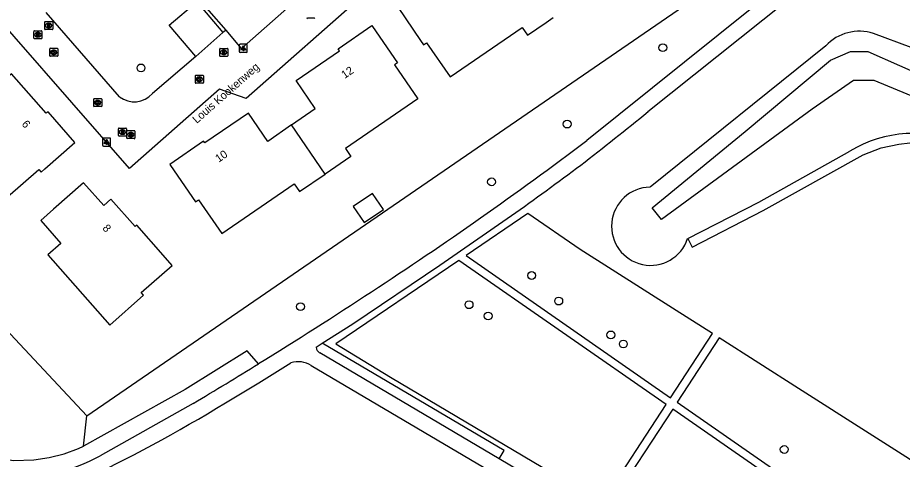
# Model space of a CAD drawing. Extents: x 159353 to 160616, y 385893 to 387321.
# Drawn here: x 160134.7 to 160245.3, y 386306.6 to 386361.8 of the extents above; entities that cross this region are included whole.
import ezdxf

# ---------------------------------------------------------------- set-up
doc = ezdxf.new("R2010")
doc.units = 0
for name, color, linetype in [('IMGEO_Boom', 7, 'Continuous'), ('IMGEO_Groenvoorziening', 7, 'Continuous'), ('IMGEO_Haag', 7, 'Continuous'), ('IMGEO_Kolk', 7, 'Continuous'), ('IMGEO_Lichtpunt', 7, 'Continuous'), ('IMGEO_Openbare_ruimte_label', 7, 'Continuous'), ('IMGEO_Pand', 7, 'Continuous'), ('IMGEO_Pand_nummerreeks', 7, 'Continuous'), ('IMGEO_Parkeervlak_open', 7, 'Continuous'), ('IMGEO_Rijbaan_lokaal_open', 7, 'Continuous'), ('IMGEO_Rioolput', 7, 'Continuous'), ('IMGEO_Voetpad_halfverhard', 7, 'Continuous'), ('IMGEO_Waterloop', 7, 'Continuous')]:
    doc.layers.add(name, color=color, linetype=linetype)

msp = doc.modelspace()

# ---------------------------------------------------------------- linework, layer by layer
at = {"layer": 'IMGEO_Boom'}
for centre in [(160215.37, 386358.02), (160150.15, 386355.49), (160203.41, 386348.48), (160193.96, 386341.26), (160198.98, 386329.57), (160202.36, 386326.38), (160170.08, 386325.68), (160191.15, 386325.92), (160193.53, 386324.52), (160208.87, 386322.15), (160210.44, 386321.02), (160230.54, 386307.85)]:
    msp.add_circle(centre, 0.489, dxfattribs=at)
at = {"layer": 'IMGEO_Groenvoorziening'}
for points in [[(160160.77, 386360.2), (160154.42, 386367.49)], [(160143.38, 386312.04), (160220.76, 386365.17)], [(160255.91, 386354.23), (160246.39, 386358.04), (160241.7, 386359.78)], [(160235.73, 386358.24), (160213.77, 386340.6)], [(160198.49, 386337.31), (160190.77, 386332.07), (160216.33, 386314.31), (160221.56, 386322.32), (160217.05, 386325.2), (160205.04, 386332.82), (160198.49, 386337.31)], [(160207.73, 386301.15), (160215.78, 386313.47), (160189.88, 386331.46), (160174.51, 386321.02), (160181.32, 386316.87), (160202.6, 386304.25), (160207.73, 386301.15)], [(160143.38, 386312.04), (160131.39, 386324.81)], [(160268.79, 386292.3), (160268.59, 386292.42), (160232.33, 386315.45), (160222.41, 386321.79), (160217.15, 386313.74), (160259.75, 386284.14), (160259.95, 386284.01), (160261.35, 386283.03)], [(160164.85, 386318.56), (160163.42, 386320.18), (160155.66, 386315.33), (160142.96, 386308.28)], [(160260.41, 386282.47), (160259.01, 386283.44), (160258.82, 386283.57), (160216.6, 386312.9), (160208.58, 386300.63), (160213.71, 386297.53), (160238.42, 386282.67), (160246.05, 386278.11)], [(160142.96, 386308.28), (160143.38, 386312.04)], [(160130.97, 386307), (160134.22, 386306.46), (160136.77, 386306.56), (160138.67, 386306.83), (160140.54, 386307.31), (160142.34, 386307.97), (160142.96, 386308.28)]]:
    msp.add_lwpolyline(points, dxfattribs=at)
for centre, radius, start, end in [((160239.91, 386354.4), 5.67, 71.5561, 137.4262), ((160213.84, 386335.72), 4.88, 90.9182, 341.6011)]:
    msp.add_arc(centre, radius, start, end, dxfattribs=at)
at = {"layer": 'IMGEO_Haag'}
for points in [[(160218.48, 386334.18), (160219.02, 386333.11), (160227.93, 386337.67), (160240.41, 386344.64), (160242.65, 386345.53), (160244.86, 386345.99), (160246.24, 386346.12)], [(160218.48, 386334.18), (160227.36, 386338.73), (160238.75, 386345.09)], [(160194.91, 386306.66), (160195.52, 386307.7), (160172.8, 386321.12)]]:
    msp.add_lwpolyline(points, dxfattribs=at)
msp.add_arc((160246.7, 386332.01), 15.31, 65.4867, 121.2918, dxfattribs=at)
at = {"layer": 'IMGEO_Kolk'}
for p, q in [((160171.79, 386361.69), (160170.94, 386361.69)), ((160138.74, 386357.02), (160138.74, 386357.87)), ((160138.81, 386357.94), (160139.67, 386357.94)), ((160139.74, 386357.87), (160139.74, 386357.02)), ((160139.67, 386356.94), (160138.81, 386356.94)), ((160139.23, 386357.72), (160139.25, 386357.72)), ((160139.25, 386357.16), (160139.23, 386357.16)), ((160156.94, 386353.66), (160156.94, 386354.51)), ((160157.01, 386354.59), (160157.86, 386354.59)), ((160157.94, 386354.51), (160157.94, 386353.66)), ((160157.86, 386353.58), (160157.01, 386353.58)), ((160157.42, 386354.36), (160157.45, 386354.36)), ((160157.45, 386353.81), (160157.42, 386353.81)), ((160144.24, 386350.73), (160144.24, 386351.58)), ((160144.31, 386351.66), (160145.16, 386351.66)), ((160144.72, 386351.44), (160144.75, 386351.44)), ((160145.24, 386351.58), (160145.24, 386350.73)), ((160145.16, 386350.66), (160144.31, 386350.66)), ((160144.75, 386350.88), (160144.72, 386350.88))]:
    msp.add_line(p, q, dxfattribs=at)
for points in [[(160171.79, 386361.69), (160170.94, 386361.69)], [(160138.74, 386357.02), (160138.74, 386357.87)], [(160138.81, 386357.94), (160139.67, 386357.94)], [(160139.74, 386357.87), (160139.74, 386357.02)], [(160139.67, 386356.94), (160138.81, 386356.94)], [(160139.06, 386357.64), (160139.18, 386357.64), (160139.18, 386357.49), (160139.31, 386357.64), (160139.48, 386357.64), (160139.33, 386357.49), (160139.48, 386357.24), (160139.33, 386357.24), (160139.25, 386357.41), (160139.18, 386357.34), (160139.18, 386357.24), (160139.06, 386357.24), (160139.06, 386357.64)], [(160156.94, 386353.66), (160156.94, 386354.51)], [(160157.01, 386354.59), (160157.86, 386354.59)], [(160157.94, 386354.51), (160157.94, 386353.66)], [(160157.86, 386353.58), (160157.01, 386353.58)], [(160157.26, 386354.28), (160157.38, 386354.28), (160157.38, 386354.13), (160157.51, 386354.28), (160157.67, 386354.28), (160157.53, 386354.13), (160157.68, 386353.88), (160157.53, 386353.88), (160157.44, 386354.05), (160157.38, 386353.98), (160157.38, 386353.88), (160157.26, 386353.88), (160157.26, 386354.28)], [(160144.24, 386350.73), (160144.24, 386351.58)], [(160144.31, 386351.66), (160145.16, 386351.66)], [(160144.56, 386351.36), (160144.68, 386351.36), (160144.68, 386351.21), (160144.81, 386351.36), (160144.97, 386351.36), (160144.83, 386351.21), (160144.98, 386350.96), (160144.83, 386350.96), (160144.74, 386351.12), (160144.68, 386351.06), (160144.68, 386350.96), (160144.56, 386350.96), (160144.56, 386351.36)], [(160145.24, 386351.58), (160145.24, 386350.73)], [(160145.16, 386350.66), (160144.31, 386350.66)]]:
    msp.add_lwpolyline(points, dxfattribs=at)
for centre, start, end in [((160170.94, 386361.76), 181.552, 268.448), ((160170.94, 386361.76), 181.552, 268.448), ((160171.79, 386361.76), 271.552, 358.448), ((160171.79, 386361.76), 271.552, 358.448), ((160138.82, 386357.87), 91.552, 178.448), ((160138.82, 386357.87), 91.552, 178.448), ((160139.66, 386357.87), 1.552, 88.448), ((160139.66, 386357.87), 1.552, 88.448), ((160138.82, 386357.02), 181.552, 268.448), ((160138.82, 386357.02), 181.552, 268.448), ((160139.66, 386357.02), 271.552, 358.448), ((160139.66, 386357.02), 271.552, 358.448), ((160157.01, 386354.51), 91.552, 178.448), ((160157.01, 386354.51), 91.552, 178.448), ((160157.86, 386354.51), 1.552, 88.448), ((160157.86, 386354.51), 1.552, 88.448), ((160157.01, 386353.66), 181.552, 268.448), ((160157.01, 386353.66), 181.552, 268.448), ((160157.86, 386353.66), 271.552, 358.448), ((160157.86, 386353.66), 271.552, 358.448), ((160144.31, 386351.58), 91.552, 178.448), ((160144.31, 386351.58), 91.552, 178.448), ((160145.16, 386351.58), 1.552, 88.448), ((160145.16, 386351.58), 1.552, 88.448), ((160144.31, 386350.73), 181.552, 268.448), ((160144.31, 386350.73), 181.552, 268.448), ((160145.16, 386350.73), 271.552, 358.448), ((160145.16, 386350.73), 271.552, 358.448)]:
    msp.add_arc(centre, 0.0765, start, end, dxfattribs=at)
for centre, major_axis, ratio, start_param, end_param in [((160139.23, 386357.44), (-0.387, 0.002), 0.722429, 4.712389, 7.853982), ((160139.25, 386357.44), (-0.39, 0.002), 0.717154, 1.570796, 4.712389), ((160157.42, 386354.08), (-0.387, 0.002), 0.722429, 4.712389, 7.853982), ((160157.45, 386354.08), (-0.39, 0.002), 0.717154, 1.570796, 4.712389), ((160144.72, 386351.16), (-0.387, 0.002), 0.722429, 4.712389, 7.853982), ((160144.75, 386351.16), (-0.39, 0.002), 0.717154, 1.570796, 4.712389)]:
    msp.add_ellipse(centre, major_axis=major_axis, ratio=ratio, start_param=start_param, end_param=end_param, dxfattribs=at)
at = {"layer": 'IMGEO_Lichtpunt'}
for p, q in [((160162.43, 386358.34), (160162.43, 386357.53)), ((160162.43, 386358.34), (160162.43, 386357.53)), ((160163.33, 386358.44), (160162.52, 386358.44)), ((160163.33, 386358.44), (160162.52, 386358.44)), ((160163.42, 386357.53), (160163.42, 386358.34)), ((160163.42, 386357.53), (160163.42, 386358.34)), ((160162.52, 386357.44), (160163.33, 386357.44)), ((160162.52, 386357.44), (160163.33, 386357.44)), ((160146.25, 386346.74), (160145.44, 386346.74)), ((160146.25, 386346.74), (160145.44, 386346.74)), ((160145.35, 386346.64), (160145.35, 386345.84)), ((160145.35, 386346.64), (160145.35, 386345.84)), ((160145.44, 386345.74), (160146.25, 386345.74)), ((160145.44, 386345.74), (160146.25, 386345.74)), ((160146.35, 386345.84), (160146.35, 386346.64)), ((160146.35, 386345.84), (160146.35, 386346.64))]:
    msp.add_line(p, q, dxfattribs=at)
for points in [[(160162.8, 386358), (160162.84, 386357.98), (160162.65, 386357.71), (160162.61, 386357.74), (160162.8, 386358)], [(160162.9, 386357.96), (160162.95, 386357.96), (160162.95, 386357.63), (160162.9, 386357.63), (160162.9, 386357.96)], [(160163.01, 386357.98), (160163.05, 386358), (160163.24, 386357.74), (160163.2, 386357.71), (160163.01, 386357.98)], [(160145.72, 386346.31), (160145.76, 386346.28), (160145.58, 386346.02), (160145.54, 386346.04), (160145.72, 386346.31)], [(160145.83, 386346.26), (160145.87, 386346.26), (160145.87, 386345.94), (160145.83, 386345.94), (160145.83, 386346.26)], [(160145.94, 386346.28), (160145.97, 386346.31), (160146.16, 386346.04), (160146.12, 386346.02), (160145.94, 386346.28)]]:
    msp.add_lwpolyline(points, dxfattribs=at)
for centre in [(160162.93, 386358.14), (160145.85, 386346.44)]:
    msp.add_circle(centre, 0.0994, dxfattribs=at)
for centre, start, end in [((160162.52, 386358.34), 90, 180), ((160162.52, 386358.34), 90, 180), ((160163.33, 386358.34), 0, 90), ((160163.33, 386358.34), 0, 90), ((160162.52, 386357.53), 180, 270), ((160162.52, 386357.53), 180, 270), ((160163.33, 386357.53), 270, 0), ((160163.33, 386357.53), 270, 360), ((160145.44, 386346.64), 90, 180), ((160145.44, 386346.64), 90, 180), ((160146.25, 386346.64), 0, 90), ((160146.25, 386346.64), 0, 90), ((160145.44, 386345.84), 180, 270), ((160145.44, 386345.84), 180, 270), ((160146.25, 386345.84), 270, 0), ((160146.25, 386345.84), 270, 360)]:
    msp.add_arc(centre, 0.0946, start, end, dxfattribs=at)
at = {"layer": 'IMGEO_Pand'}
for points in [[(160197.61, 386367.69), (160194.65, 386365.65), (160192.06, 386369.4), (160186.63, 386365.67), (160186.47, 386365.91), (160182.27, 386363.03), (160185.1, 386358.91), (160185.46, 386358.38), (160185.83, 386358.64), (160188.78, 386354.36), (160197.8, 386360.56), (160198.47, 386359.59), (160200.78, 386361.18), (160201.67, 386361.79)], [(160168.95, 386348.37), (160171.91, 386350.41), (160169.53, 386353.91), (160174.94, 386357.63), (160174.79, 386357.88), (160179.01, 386360.77), (160181.84, 386356.65), (160182.2, 386356.13), (160181.83, 386355.87), (160184.74, 386351.63), (160175.72, 386345.42), (160176.39, 386344.45), (160173.16, 386342.24)], [(160122.81, 386349.79), (160125.36, 386346.87), (160126.25, 386347.65), (160133.46, 386339.41), (160137.36, 386342.82), (160137.65, 386342.49), (160138.12, 386342.9), (160141.89, 386346.19), (160138.54, 386350.01), (160138.31, 386349.83), (160133.96, 386354.77), (160130.76, 386351.98), (160128.39, 386354.68)], [(160168.95, 386348.37), (160165.99, 386346.32), (160163.57, 386349.83), (160158.11, 386346.12), (160157.97, 386346.33), (160153.77, 386343.43), (160156.6, 386339.31), (160156.96, 386338.79), (160157.33, 386339.04), (160160.25, 386334.8), (160169.29, 386341.01), (160169.96, 386340.04), (160173.16, 386342.24)], [(160173.16, 386342.24), (160168.95, 386348.37)], [(160150.47, 386327.1), (160150.17, 386327.44), (160154.04, 386330.84), (160152.92, 386332.12), (160149.61, 386335.87), (160149.41, 386335.69), (160146.39, 386339.1), (160145.48, 386338.3), (160142.97, 386341.15), (160139.22, 386337.85), (160137.61, 386336.43), (160140.12, 386333.58), (160138.5, 386332.15), (160146.23, 386323.37), (160150.47, 386327.1)], [(160180.45, 386337.83), (160179.07, 386339.83), (160176.68, 386338.19), (160178.05, 386336.19), (160180.45, 386337.83)]]:
    msp.add_lwpolyline(points, dxfattribs=at)
at = {"layer": 'IMGEO_Parkeervlak_open'}
msp.add_lwpolyline([(160156.99, 386356.93), (160153.67, 386360.81), (160157.12, 386363.75), (160160.38, 386359.93)], dxfattribs=at)
at = {"layer": 'IMGEO_Rijbaan_lokaal_open'}
for points in [[(160199.4, 386380.85), (160179.64, 386363.49), (160178.33, 386364.97), (160163.29, 386351.69), (160159.97, 386352.84), (160148.7, 386342.92), (160127.04, 386367.69), (160141.86, 386380.85), (160145.8, 386393.31)], [(160197.43, 386383.17), (160193.87, 386380.06), (160192.54, 386381.54), (160183.44, 386373.54), (160182.14, 386375.08), (160162.71, 386357.93), (160160.77, 386360.2)], [(160147.47, 386351.9), (160138.29, 386362.43)], [(160160.77, 386360.2), (160160.38, 386359.93)], [(160160.38, 386359.93), (160156.99, 386356.93)], [(160156.99, 386356.93), (160151.57, 386352.3)]]:
    msp.add_lwpolyline(points, dxfattribs=at)
msp.add_arc((160149.31, 386354.22), 2.96, 231.5618, 319.6293, dxfattribs=at)
at = {"layer": 'IMGEO_Rioolput'}
for p, q in [((160138.11, 386360.35), (160138.11, 386361.21)), ((160138.18, 386361.28), (160139.03, 386361.28)), ((160139.11, 386361.21), (160139.11, 386360.35)), ((160136.76, 386359.21), (160136.76, 386360.06)), ((160136.84, 386360.13), (160137.69, 386360.13)), ((160137.76, 386360.06), (160137.76, 386359.21)), ((160139.03, 386360.28), (160138.18, 386360.28)), ((160138.62, 386360.5), (160138.59, 386360.5)), ((160138.6, 386361.06), (160138.62, 386361.06)), ((160137.69, 386359.13), (160136.84, 386359.13)), ((160137.25, 386359.91), (160137.27, 386359.91)), ((160137.27, 386359.35), (160137.25, 386359.35)), ((160159.98, 386357.01), (160159.98, 386357.86)), ((160160.06, 386357.93), (160160.91, 386357.93)), ((160160.98, 386357.86), (160160.98, 386357.01)), ((160160.91, 386356.93), (160160.06, 386356.93)), ((160160.47, 386357.71), (160160.49, 386357.71)), ((160160.49, 386357.15), (160160.47, 386357.15)), ((160147.32, 386347.05), (160147.32, 386347.9)), ((160147.39, 386347.98), (160148.25, 386347.98)), ((160148.32, 386347.9), (160148.32, 386347.05)), ((160148.25, 386346.98), (160147.39, 386346.98)), ((160147.83, 386347.2), (160147.8, 386347.2)), ((160147.81, 386347.76), (160147.83, 386347.76)), ((160148.38, 386346.73), (160148.38, 386347.58)), ((160148.45, 386347.66), (160149.31, 386347.66)), ((160148.89, 386346.88), (160148.86, 386346.88)), ((160148.87, 386347.44), (160148.89, 386347.44)), ((160149.38, 386347.58), (160149.38, 386346.73)), ((160149.31, 386346.66), (160148.45, 386346.66))]:
    msp.add_line(p, q, dxfattribs=at)
for points in [[(160138.11, 386360.35), (160138.11, 386361.21)], [(160138.18, 386361.28), (160139.03, 386361.28)], [(160139.11, 386361.21), (160139.11, 386360.35)], [(160136.76, 386359.21), (160136.76, 386360.06)], [(160136.84, 386360.13), (160137.69, 386360.13)], [(160137.76, 386360.06), (160137.76, 386359.21)], [(160139.03, 386360.28), (160138.18, 386360.28)], [(160138.7, 386360.98), (160138.44, 386360.98), (160138.44, 386360.58)], [(160138.44, 386360.58), (160138.57, 386360.58), (160138.57, 386360.74), (160138.58, 386360.74)], [(160138.62, 386360.9), (160138.57, 386360.9), (160138.57, 386360.82)], [(160138.57, 386360.82), (160138.62, 386360.82)], [(160138.63, 386360.71), (160138.7, 386360.58), (160138.84, 386360.58), (160138.77, 386360.71)], [(160137.69, 386359.13), (160136.84, 386359.13)], [(160137.35, 386359.83), (160137.1, 386359.83), (160137.1, 386359.43)], [(160137.1, 386359.43), (160137.22, 386359.43), (160137.22, 386359.59), (160137.23, 386359.59)], [(160137.28, 386359.75), (160137.22, 386359.75), (160137.22, 386359.67)], [(160137.22, 386359.67), (160137.27, 386359.67)], [(160137.28, 386359.56), (160137.35, 386359.43), (160137.49, 386359.43), (160137.43, 386359.56)], [(160159.98, 386357.01), (160159.98, 386357.86)], [(160160.06, 386357.93), (160160.91, 386357.93)], [(160160.98, 386357.86), (160160.98, 386357.01)], [(160160.91, 386356.93), (160160.06, 386356.93)], [(160160.57, 386357.63), (160160.32, 386357.63), (160160.32, 386357.23)], [(160160.32, 386357.23), (160160.44, 386357.23), (160160.44, 386357.39), (160160.45, 386357.39)], [(160160.5, 386357.55), (160160.44, 386357.55), (160160.44, 386357.47)], [(160160.44, 386357.47), (160160.49, 386357.47)], [(160160.5, 386357.36), (160160.57, 386357.23), (160160.71, 386357.23), (160160.65, 386357.36)], [(160147.32, 386347.05), (160147.32, 386347.9)], [(160147.39, 386347.98), (160148.25, 386347.98)], [(160148.32, 386347.9), (160148.32, 386347.05)], [(160148.25, 386346.98), (160147.39, 386346.98)], [(160147.91, 386347.68), (160147.66, 386347.68), (160147.66, 386347.28)], [(160147.66, 386347.28), (160147.78, 386347.28), (160147.78, 386347.44), (160147.79, 386347.44)], [(160147.83, 386347.6), (160147.78, 386347.6), (160147.78, 386347.52)], [(160147.78, 386347.52), (160147.83, 386347.52)], [(160147.84, 386347.41), (160147.91, 386347.28), (160148.05, 386347.28), (160147.98, 386347.4)], [(160148.38, 386346.73), (160148.38, 386347.58)], [(160148.45, 386347.66), (160149.31, 386347.66)], [(160148.97, 386347.35), (160148.72, 386347.36), (160148.72, 386346.96)], [(160148.72, 386346.96), (160148.84, 386346.96), (160148.84, 386347.12), (160148.85, 386347.12)], [(160148.89, 386347.28), (160148.84, 386347.28), (160148.84, 386347.19)], [(160148.84, 386347.19), (160148.89, 386347.19)], [(160148.9, 386347.09), (160148.97, 386346.96), (160149.11, 386346.96), (160149.04, 386347.08)], [(160149.38, 386347.58), (160149.38, 386346.73)], [(160149.31, 386346.66), (160148.45, 386346.66)]]:
    msp.add_lwpolyline(points, dxfattribs=at)
for centre, radius, start, end in [((160138.18, 386361.21), 0.0765, 91.552, 178.448), ((160138.18, 386361.21), 0.0765, 91.552, 178.448), ((160139.03, 386361.21), 0.0765, 1.552, 88.448), ((160139.03, 386361.21), 0.0765, 1.552, 88.448), ((160136.84, 386360.06), 0.0765, 91.552, 178.448), ((160136.84, 386360.06), 0.0765, 91.552, 178.448), ((160137.69, 386360.06), 0.0765, 1.552, 88.448), ((160137.69, 386360.06), 0.0765, 1.552, 88.448), ((160138.18, 386360.36), 0.0765, 181.552, 268.448), ((160138.18, 386360.36), 0.0765, 181.552, 268.448), ((160138.58, 386360.69), 0.0533, 26.0293, 88.6989), ((160138.63, 386360.8), 0.0964, 77.0061, 93.1865), ((160138.6, 386361.01), 0.19, 274.7715, 282.9687), ((160138.64, 386360.86), 0.0378, 276.6634, 79.6772), ((160138.7, 386360.87), 0.109, 350.3612, 89.416), ((160138.69, 386360.87), 0.112, 277.5842, 350.9817), ((160138.68, 386360.65), 0.108, 29.5134, 73.7905), ((160139.03, 386360.36), 0.0765, 271.552, 358.448), ((160139.03, 386360.36), 0.0765, 271.552, 358.448), ((160136.84, 386359.21), 0.0765, 181.552, 268.448), ((160136.84, 386359.21), 0.0765, 181.552, 268.448), ((160137.23, 386359.54), 0.0533, 26.0293, 88.6989), ((160137.26, 386359.86), 0.19, 274.7715, 282.9687), ((160137.28, 386359.65), 0.0964, 77.0061, 93.1865), ((160137.3, 386359.71), 0.0378, 276.6634, 79.6772), ((160137.35, 386359.72), 0.109, 350.3612, 89.416), ((160137.35, 386359.72), 0.112, 277.5842, 350.9817), ((160137.33, 386359.5), 0.108, 29.5134, 73.7905), ((160137.69, 386359.21), 0.0765, 271.552, 358.448), ((160137.69, 386359.21), 0.0765, 271.552, 358.448), ((160160.06, 386357.86), 0.0765, 91.552, 178.448), ((160160.06, 386357.86), 0.0765, 91.552, 178.448), ((160160.91, 386357.86), 0.0765, 1.552, 88.448), ((160160.91, 386357.86), 0.0765, 1.552, 88.448), ((160160.06, 386357.01), 0.0765, 181.552, 268.448), ((160160.06, 386357.01), 0.0765, 181.552, 268.448), ((160160.45, 386357.34), 0.0533, 26.0293, 88.6989), ((160160.48, 386357.66), 0.19, 274.7715, 282.9687), ((160160.5, 386357.45), 0.0964, 77.0061, 93.1865), ((160160.52, 386357.51), 0.0378, 276.6634, 79.6772), ((160160.57, 386357.52), 0.109, 350.3612, 89.416), ((160160.57, 386357.52), 0.112, 277.5842, 350.9817), ((160160.55, 386357.3), 0.108, 29.5134, 73.7905), ((160160.91, 386357.01), 0.0765, 271.552, 358.448), ((160160.91, 386357.01), 0.0765, 271.552, 358.448), ((160147.4, 386347.9), 0.0765, 91.552, 178.448), ((160147.4, 386347.9), 0.0765, 91.552, 178.448), ((160148.24, 386347.9), 0.0765, 1.552, 88.448), ((160148.24, 386347.9), 0.0765, 1.552, 88.448), ((160147.4, 386347.05), 0.0765, 181.552, 268.448), ((160147.4, 386347.05), 0.0765, 181.552, 268.448), ((160147.79, 386347.39), 0.0533, 26.0293, 88.6989), ((160147.84, 386347.5), 0.0964, 77.0061, 93.1865), ((160147.82, 386347.71), 0.19, 274.7715, 282.9687), ((160147.85, 386347.56), 0.0378, 276.6634, 79.6772), ((160147.91, 386347.57), 0.109, 350.3612, 89.416), ((160147.91, 386347.57), 0.112, 277.5842, 350.9817), ((160147.89, 386347.35), 0.108, 29.5134, 73.7905), ((160148.24, 386347.05), 0.0765, 271.552, 358.448), ((160148.24, 386347.05), 0.0765, 271.552, 358.448), ((160148.46, 386347.58), 0.0765, 91.552, 178.448), ((160148.46, 386347.58), 0.0765, 91.552, 178.448), ((160148.46, 386346.73), 0.0765, 181.552, 268.448), ((160148.46, 386346.73), 0.0765, 181.552, 268.448), ((160148.85, 386347.07), 0.0533, 26.0293, 88.6989), ((160148.9, 386347.18), 0.0964, 77.0061, 93.1865), ((160148.88, 386347.38), 0.19, 274.7715, 282.9687), ((160148.91, 386347.24), 0.0378, 276.6634, 79.6772), ((160148.97, 386347.25), 0.109, 350.3612, 89.416), ((160148.97, 386347.24), 0.112, 277.5842, 350.9817), ((160148.95, 386347.03), 0.108, 29.5134, 73.7905), ((160149.3, 386347.58), 0.0765, 1.552, 88.448), ((160149.3, 386347.58), 0.0765, 1.552, 88.448), ((160149.3, 386346.73), 0.0765, 271.552, 358.448), ((160149.3, 386346.73), 0.0765, 271.552, 358.448)]:
    msp.add_arc(centre, radius, start, end, dxfattribs=at)
for centre, major_axis, ratio, start_param, end_param in [((160138.59, 386360.78), (-0.387, 0.002), 0.722429, 4.712389, 7.853982), ((160138.62, 386360.78), (-0.39, 0.002), 0.717154, 1.570796, 4.712389), ((160137.25, 386359.63), (-0.387, 0.002), 0.722429, 4.712389, 7.853982), ((160137.27, 386359.63), (-0.39, 0.002), 0.717154, 1.570796, 4.712389), ((160160.47, 386357.43), (-0.387, 0.002), 0.722429, 4.712389, 7.853982), ((160160.49, 386357.43), (-0.39, 0.002), 0.717154, 1.570796, 4.712389), ((160147.81, 386347.48), (-0.387, 0.002), 0.722429, 4.712389, 7.853982), ((160147.83, 386347.48), (-0.39, 0.002), 0.717154, 1.570796, 4.712389), ((160148.87, 386347.16), (-0.387, 0.002), 0.722429, 4.712389, 7.853982), ((160148.89, 386347.16), (-0.39, 0.002), 0.717154, 1.570796, 4.712389)]:
    msp.add_ellipse(centre, major_axis=major_axis, ratio=ratio, start_param=start_param, end_param=end_param, dxfattribs=at)
at = {"layer": 'IMGEO_Voetpad_halfverhard'}
for points in [[(160213.51, 386350.04), (160239.36, 386370.69)], [(160226.3, 386362.8), (160205.85, 386346.42)], [(160172.8, 386321.12), (160176.62, 386323.54), (160187.5, 386330.88), (160196.44, 386337.05)], [(160172.02, 386320.62), (160172.8, 386321.12)], [(160194.91, 386306.66), (160172.51, 386319.9)], [(160160.71, 386313.66), (160164.88, 386316.15), (160168.89, 386318.65)], [(160171.43, 386318.35), (160210.32, 386295.41)], [(160156.68, 386313.6), (160145.04, 386307.07)], [(160212.2, 386296.46), (160194.91, 386306.66)]]:
    msp.add_lwpolyline(points, dxfattribs=at)
for centre, radius, start, end in [((160044.98, 386553.9), 264.51, 304.9323, 309.5809), ((159915.03, 386732.35), 483.24, 303.104, 306.9998), ((159845.46, 386835.51), 607.65, 301.70909, 303.28636), ((160172.88, 386320.67), 0.862, 183.5185, 244.3351), ((159842.1, 386840.82), 613.94, 300.82296, 301.71512), ((160169.82, 386315.67), 3.13, 59.0168, 107.3439), ((160056.1, 386485.38), 201.07, 295.3567, 301.35), ((160135.1, 386324.83), 20.35, 265.7864, 299.2309)]:
    msp.add_arc(centre, radius, start, end, dxfattribs=at)
at = {"layer": 'IMGEO_Waterloop'}
msp.add_lwpolyline([(160290.96, 386306.26), (160293.26, 386309.07), (160286.53, 386324.48), (160282.96, 386331.62), (160271.04, 386341.92), (160247.13, 386351.71), (160241.77, 386353.92), (160239.21, 386353.92), (160234.02, 386350.35), (160215.21, 386336.56), (160214.02, 386338.01), (160225.64, 386347.54), (160236.32, 386356.48), (160238.83, 386357.54), (160241, 386357.54), (160256.83, 386350.56), (160272.15, 386344.35), (160280.23, 386337.71), (160285.98, 386330.9), (160289.77, 386324.65), (160298.49, 386309.26), (160318.98, 386321.84), (160319.91, 386320.58), (160266.43, 386287.6)], dxfattribs=at)

# ---------------------------------------------------------------- texts
at = {"layer": 'IMGEO_Openbare_ruimte_label'}
msp.add_text('Louis Kookenweg', height=1, rotation=41.4717, dxfattribs=at).set_placement((160157.12, 386348.49))
at = {"layer": 'IMGEO_Pand_nummerreeks'}
for s, rotation, p in [('12', 34.4645, (160175.6, 386354.1)), ('6', 311.2981, (160135.17, 386348.43)), ('10', 34.6468, (160159.85, 386343.64)), ('8', 311.4453, (160145.26, 386335.43))]:
    msp.add_text(s, height=1, rotation=rotation, dxfattribs=at).set_placement(p)

doc.saveas('drawing.dxf')
